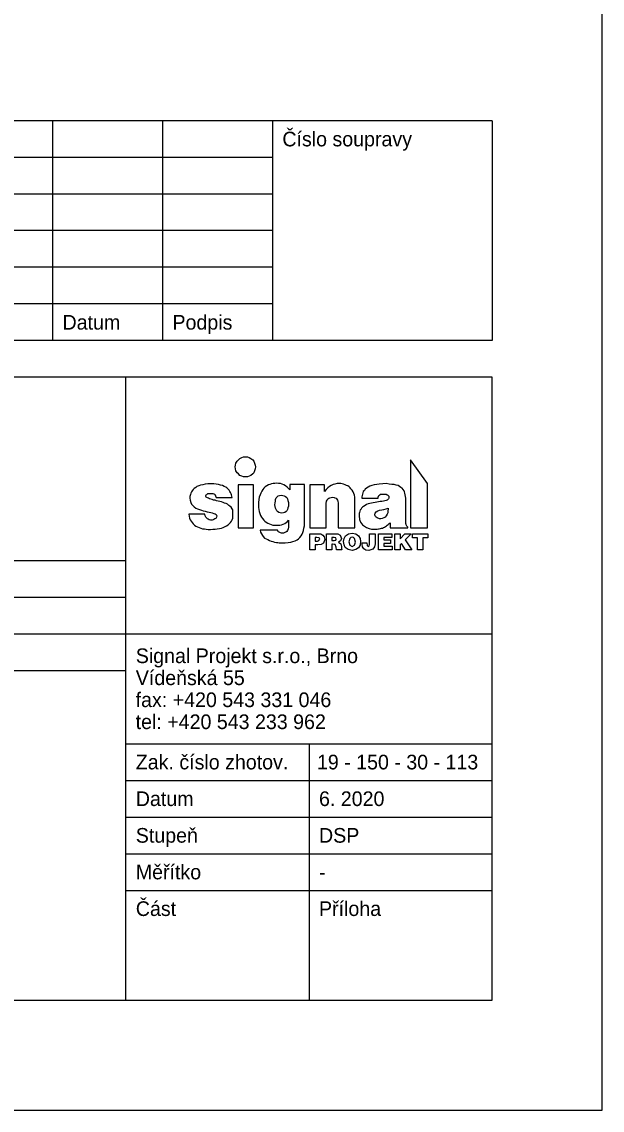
# Model space of a CAD drawing. Extents: x -790471 to -790261, y -983478 to -983181.
# Drawn here: x -790339.8 to -790260.6, y -983477.6 to -983329.1 of the extents above; entities that cross this region are included whole.
import ezdxf

# ---------------------------------------------------------------- set-up
doc = ezdxf.new("R2010")
doc.units = 0
for name, color, linetype in [('Info o rozpiskách', 7, 'Continuous'), ('popis', 7, 'Continuous'), ('Ramečky', 7, 'Continuous'), ('Rámečky-tisk', 7, 'Continuous'), ('Text', 7, 'Continuous')]:
    doc.layers.add(name, color=color, linetype=linetype)

msp = doc.modelspace()

# ---------------------------------------------------------------- linework, layer by layer
at = {"layer": 'Info o rozpiskách'}
for points in [[(-790309.25, -983388.46), (-790308.98, -983388.47), (-790308.76, -983388.57), (-790308.54, -983388.7), (-790308.29, -983388.87), (-790308.15, -983389.07), (-790308.03, -983389.31), (-790307.94, -983389.58), (-790307.92, -983389.84), (-790307.94, -983390.1), (-790308.03, -983390.38), (-790308.15, -983390.62), (-790308.29, -983390.79), (-790308.54, -983390.99), (-790308.76, -983391.09), (-790308.98, -983391.18), (-790309.25, -983391.2), (-790309.54, -983391.18), (-790309.79, -983391.09), (-790310.05, -983390.99), (-790310.23, -983390.79), (-790310.4, -983390.62), (-790310.57, -983390.38), (-790310.65, -983390.1), (-790310.7, -983389.84), (-790310.65, -983389.58), (-790310.57, -983389.31), (-790310.4, -983389.07), (-790310.23, -983388.87), (-790310.05, -983388.7), (-790309.79, -983388.57), (-790309.54, -983388.47), (-790309.25, -983388.46)], [(-790300.48, -983398.94), (-790299.41, -983398.94), (-790299, -983398.98), (-790298.7, -983399.13), (-790298.52, -983399.37), (-790298.46, -983399.72), (-790298.65, -983400.25), (-790298.95, -983400.42), (-790299.38, -983400.47), (-790299.75, -983400.47), (-790299.75, -983401.16), (-790300.48, -983401.16), (-790300.48, -983398.94)], [(-790299.75, -983399.44), (-790299.75, -983399.95), (-790299.43, -983399.95), (-790299.25, -983399.89), (-790299.15, -983399.69), (-790299.23, -983399.52), (-790299.54, -983399.44), (-790299.75, -983399.44)], [(-790298.24, -983398.94), (-790297.16, -983398.94), (-790296.67, -983398.98), (-790296.35, -983399.13), (-790296.19, -983399.58), (-790296.3, -983399.93), (-790296.56, -983400.12), (-790296.24, -983400.34), (-790296.19, -983400.71), (-790296.19, -983400.88), (-790296.17, -983401.05), (-790296.11, -983401.11), (-790296.11, -983401.16), (-790296.86, -983401.16), (-790296.9, -983400.77), (-790297.03, -983400.42), (-790297.18, -983400.4), (-790297.4, -983400.38), (-790297.51, -983400.38), (-790297.51, -983401.16), (-790298.24, -983401.16), (-790298.24, -983398.94)], [(-790297.51, -983399.44), (-790297.51, -983399.89), (-790297.19, -983399.89), (-790296.93, -983399.82), (-790296.88, -983399.69), (-790296.95, -983399.52), (-790297.16, -983399.44), (-790297.51, -983399.44)], [(-790294.73, -983398.89), (-790294.23, -983398.96), (-790293.84, -983399.22), (-790293.63, -983399.59), (-790293.56, -983400.02), (-790293.63, -983400.49), (-790293.85, -983400.86), (-790294.23, -983401.12), (-790294.73, -983401.22), (-790295.25, -983401.12), (-790295.65, -983400.84), (-790295.83, -983400.47), (-790295.91, -983400.02), (-790295.83, -983399.58), (-790295.61, -983399.22), (-790295.23, -983398.96), (-790294.73, -983398.89)], [(-790294.73, -983399.43), (-790294.92, -983399.46), (-790295.05, -983399.58), (-790295.16, -983400.04), (-790295.05, -983400.53), (-790294.73, -983400.68), (-790294.38, -983400.49), (-790294.28, -983400.08), (-790294.4, -983399.61), (-790294.53, -983399.46), (-790294.73, -983399.43)], [(-790292.33, -983398.94), (-790291.6, -983398.94), (-790291.6, -983400.32), (-790291.67, -983400.75), (-790291.88, -983401.05), (-790292.46, -983401.22), (-790292.83, -983401.18), (-790293.11, -983401.03), (-790293.29, -983400.75), (-790293.37, -983400.36), (-790293.35, -983400.19), (-790292.7, -983400.19), (-790292.66, -983400.56), (-790292.51, -983400.68), (-790292.38, -983400.6), (-790292.33, -983400.42), (-790292.33, -983398.94)], [(-790291.13, -983398.94), (-790289.32, -983398.94), (-790289.32, -983399.44), (-790290.4, -983399.44), (-790290.4, -983399.78), (-790289.49, -983399.78), (-790289.49, -983400.3), (-790290.4, -983400.3), (-790290.4, -983400.64), (-790289.27, -983400.64), (-790289.27, -983401.16), (-790291.13, -983401.16), (-790291.13, -983398.94)], [(-790288.91, -983398.94), (-790288.16, -983398.94), (-790288.16, -983399.65), (-790287.53, -983398.94), (-790286.67, -983398.94), (-790287.49, -983399.78), (-790286.58, -983401.16), (-790287.46, -983401.16), (-790288, -983400.28), (-790288.16, -983400.45), (-790288.16, -983401.16), (-790288.91, -983401.16), (-790288.91, -983398.94)], [(-790286.47, -983398.94), (-790284.41, -983398.94), (-790284.41, -983399.52), (-790285.07, -983399.52), (-790285.07, -983401.16), (-790285.8, -983401.16), (-790285.8, -983399.52), (-790286.47, -983399.52), (-790286.47, -983398.94)]]:
    msp.add_lwpolyline(points, dxfattribs=at)
at = {"layer": 'popis'}
for points in [[(-790286.77, -983388.87), (-790286.77, -983398.14), (-790284.45, -983398.14), (-790284.45, -983392.11), (-790286.77, -983388.87)], [(-790313.29, -983394.02), (-790311.09, -983394.02), (-790311.15, -983393.83), (-790311.19, -983393.66), (-790311.24, -983393.49), (-790311.32, -983393.33), (-790311.41, -983393.18), (-790311.52, -983393.01), (-790311.63, -983392.86), (-790311.8, -983392.69), (-790311.97, -983392.6), (-790312.17, -983392.49), (-790312.4, -983392.39), (-790312.66, -983392.3), (-790312.94, -983392.24), (-790313.26, -983392.19), (-790313.61, -983392.15), (-790314, -983392.13), (-790314.4, -983392.15), (-790314.77, -983392.19), (-790315.09, -983392.26), (-790315.4, -983392.32), (-790315.66, -983392.41), (-790315.89, -983392.52), (-790316.07, -983392.65), (-790316.26, -983392.78), (-790316.43, -983392.93), (-790316.54, -983393.08), (-790316.65, -983393.23), (-790316.71, -983393.4), (-790316.78, -983393.59), (-790316.82, -983393.75), (-790316.86, -983393.89), (-790316.86, -983394.09), (-790316.8, -983394.39), (-790316.71, -983394.69), (-790316.62, -983394.91), (-790316.43, -983395.15), (-790316.26, -983395.28), (-790316.06, -983395.45), (-790315.81, -983395.56), (-790315.55, -983395.64), (-790315.29, -983395.73), (-790315.03, -983395.81), (-790314.77, -983395.88), (-790314.51, -983395.96), (-790314.25, -983395.99), (-790314.02, -983396.03), (-790313.8, -983396.09), (-790313.59, -983396.18), (-790313.39, -983396.25), (-790313.29, -983396.33), (-790313.22, -983396.42), (-790313.2, -983396.52), (-790313.24, -983396.68), (-790313.29, -983396.76), (-790313.33, -983396.85), (-790313.44, -983396.93), (-790313.57, -983397), (-790313.67, -983397.04), (-790313.8, -983397.08), (-790313.93, -983397.08), (-790314.06, -983397.08), (-790314.21, -983397.04), (-790314.38, -983396.98), (-790314.47, -983396.93), (-790314.6, -983396.8), (-790314.69, -983396.68), (-790314.77, -983396.5), (-790314.82, -983396.27), (-790317.01, -983396.27), (-790316.97, -983396.57), (-790316.9, -983396.83), (-790316.8, -983397.06), (-790316.69, -983397.24), (-790316.56, -983397.43), (-790316.41, -983397.6), (-790316.24, -983397.77), (-790316.06, -983397.9), (-790315.83, -983398.01), (-790315.61, -983398.12), (-790315.38, -983398.2), (-790315.14, -983398.27), (-790314.86, -983398.29), (-790314.62, -983398.34), (-790314.38, -983398.36), (-790314.06, -983398.36), (-790313.74, -983398.34), (-790313.43, -983398.34), (-790313.13, -983398.29), (-790312.83, -983398.23), (-790312.55, -983398.18), (-790312.31, -983398.08), (-790312.06, -983397.95), (-790311.86, -983397.86), (-790311.65, -983397.73), (-790311.47, -983397.56), (-790311.34, -983397.41), (-790311.2, -983397.24), (-790311.09, -983397.06), (-790311.02, -983396.83), (-790311, -983396.61), (-790311, -983396.39), (-790311, -983396.33), (-790311, -983396.27), (-790311, -983396.22), (-790311, -983396.16), (-790311, -983396.09), (-790311, -983396.03), (-790311, -983395.99), (-790311, -983395.96), (-790311.02, -983395.71), (-790311.11, -983395.53), (-790311.24, -983395.34), (-790311.39, -983395.21), (-790311.54, -983395.08), (-790311.73, -983394.93), (-790311.9, -983394.84), (-790312.12, -983394.76), (-790312.32, -983394.69), (-790312.55, -983394.61), (-790312.77, -983394.54), (-790312.98, -983394.5), (-790313.22, -983394.44), (-790313.43, -983394.39), (-790313.65, -983394.35), (-790313.84, -983394.3), (-790314.02, -983394.22), (-790314.19, -983394.18), (-790314.32, -983394.11), (-790314.45, -983394.07), (-790314.53, -983394.02), (-790314.64, -983393.94), (-790314.67, -983393.89), (-790314.67, -983393.81), (-790314.67, -983393.74), (-790314.64, -983393.66), (-790314.56, -983393.59), (-790314.49, -983393.55), (-790314.41, -983393.47), (-790314.28, -983393.47), (-790314.13, -983393.44), (-790314, -983393.44), (-790313.85, -983393.44), (-790313.72, -983393.47), (-790313.61, -983393.49), (-790313.5, -983393.55), (-790313.43, -983393.64), (-790313.39, -983393.74), (-790313.31, -983393.85), (-790313.29, -983394.02)], [(-790303.24, -983392.24), (-790303.24, -983392.97), (-790303.41, -983392.77), (-790303.59, -983392.6), (-790303.8, -983392.43), (-790304.04, -983392.28), (-790304.28, -983392.17), (-790304.51, -983392.11), (-790304.75, -983392.08), (-790305.03, -983392.06), (-790305.29, -983392.08), (-790305.48, -983392.09), (-790305.74, -983392.13), (-790305.93, -983392.23), (-790306.15, -983392.28), (-790306.35, -983392.43), (-790306.58, -983392.54), (-790306.76, -983392.73), (-790306.91, -983392.92), (-790307.06, -983393.16), (-790307.19, -983393.4), (-790307.29, -983393.64), (-790307.4, -983393.96), (-790307.47, -983394.3), (-790307.51, -983394.67), (-790307.51, -983395.06), (-790307.51, -983395.38), (-790307.47, -983395.66), (-790307.4, -983395.92), (-790307.32, -983396.2), (-790307.23, -983396.44), (-790307.1, -983396.68), (-790306.93, -983396.89), (-790306.78, -983397.08), (-790306.62, -983397.24), (-790306.45, -983397.39), (-790306.22, -983397.52), (-790306, -983397.62), (-790305.78, -983397.71), (-790305.53, -983397.77), (-790305.29, -983397.8), (-790305.03, -983397.8), (-790304.81, -983397.8), (-790304.6, -983397.77), (-790304.34, -983397.73), (-790304.12, -983397.64), (-790303.91, -983397.54), (-790303.7, -983397.41), (-790303.56, -983397.28), (-790303.39, -983397.09), (-790303.39, -983397.64), (-790303.39, -983398.03), (-790303.46, -983398.29), (-790303.56, -983398.49), (-790303.63, -983398.64), (-790303.76, -983398.75), (-790303.91, -983398.79), (-790304.08, -983398.85), (-790304.26, -983398.85), (-790304.36, -983398.85), (-790304.49, -983398.83), (-790304.6, -983398.79), (-790304.69, -983398.75), (-790304.75, -983398.68), (-790304.84, -983398.61), (-790304.86, -983398.53), (-790304.9, -983398.44), (-790307.27, -983398.44), (-790307.21, -983398.74), (-790307.1, -983398.94), (-790306.97, -983399.17), (-790306.84, -983399.33), (-790306.67, -983399.54), (-790306.45, -983399.65), (-790306.24, -983399.74), (-790306, -983399.89), (-790305.78, -983399.97), (-790305.53, -983400.02), (-790305.31, -983400.08), (-790305.05, -983400.14), (-790304.84, -983400.15), (-790304.66, -983400.17), (-790304.43, -983400.19), (-790304.26, -983400.19), (-790303.85, -983400.17), (-790303.46, -983400.14), (-790303.09, -983400.08), (-790302.79, -983400.01), (-790302.49, -983399.91), (-790302.23, -983399.78), (-790302.03, -983399.63), (-790301.86, -983399.44), (-790301.69, -983399.24), (-790301.56, -983399.02), (-790301.45, -983398.77), (-790301.35, -983398.49), (-790301.32, -983398.2), (-790301.22, -983397.86), (-790301.22, -983397.51), (-790301.22, -983397.09), (-790301.22, -983392.24), (-790303.24, -983392.24)], [(-790300.5, -983392.26), (-790300.5, -983398.14), (-790298.26, -983398.14), (-790298.26, -983395.14), (-790298.26, -983394.82), (-790298.2, -983394.52), (-790298.11, -983394.35), (-790298.03, -983394.2), (-790297.9, -983394.11), (-790297.75, -983394.03), (-790297.57, -983394.02), (-790297.38, -983393.98), (-790297.19, -983394.02), (-790297.06, -983394.05), (-790296.9, -983394.11), (-790296.8, -983394.22), (-790296.73, -983394.35), (-790296.65, -983394.52), (-790296.62, -983394.78), (-790296.62, -983395.04), (-790296.62, -983398.14), (-790294.34, -983398.14), (-790294.34, -983394.59), (-790294.34, -983394.28), (-790294.36, -983393.98), (-790294.41, -983393.7), (-790294.51, -983393.44), (-790294.6, -983393.21), (-790294.71, -983393.01), (-790294.88, -983392.84), (-790294.99, -983392.67), (-790295.14, -983392.54), (-790295.31, -983392.41), (-790295.5, -983392.36), (-790295.68, -983392.26), (-790295.91, -983392.19), (-790296.09, -983392.15), (-790296.28, -983392.11), (-790296.5, -983392.11), (-790296.78, -983392.11), (-790297.06, -983392.19), (-790297.31, -983392.23), (-790297.57, -983392.36), (-790297.81, -983392.49), (-790298.05, -983392.67), (-790298.26, -983392.92), (-790298.5, -983393.18), (-790298.5, -983392.26), (-790300.5, -983392.26)], [(-790293.41, -983394.11), (-790291.19, -983394.11), (-790291.17, -983393.94), (-790291.13, -983393.81), (-790291.06, -983393.72), (-790290.96, -983393.64), (-790290.85, -983393.57), (-790290.7, -983393.53), (-790290.57, -983393.53), (-790290.42, -983393.53), (-790290.25, -983393.53), (-790290.09, -983393.55), (-790289.96, -983393.62), (-790289.88, -983393.66), (-790289.81, -983393.74), (-790289.73, -983393.81), (-790289.73, -983393.9), (-790289.69, -983394), (-790289.73, -983394.09), (-790289.75, -983394.2), (-790289.84, -983394.28), (-790289.94, -983394.35), (-790290.07, -983394.43), (-790290.25, -983394.46), (-790290.46, -983394.5), (-790290.66, -983394.54), (-790290.89, -983394.56), (-790291.13, -983394.59), (-790291.36, -983394.63), (-790291.6, -983394.67), (-790291.84, -983394.73), (-790292.08, -983394.76), (-790292.29, -983394.84), (-790292.51, -983394.87), (-790292.74, -983394.97), (-790292.96, -983395.08), (-790293.15, -983395.23), (-790293.31, -983395.32), (-790293.44, -983395.47), (-790293.54, -983395.62), (-790293.61, -983395.71), (-790293.67, -983395.88), (-790293.7, -983396.03), (-790293.74, -983396.2), (-790293.76, -983396.35), (-790293.76, -983396.52), (-790293.7, -983397), (-790293.56, -983397.39), (-790293.31, -983397.73), (-790293.05, -983397.93), (-790292.74, -983398.12), (-790292.38, -983398.25), (-790292.06, -983398.33), (-790291.73, -983398.34), (-790291.58, -983398.34), (-790291.45, -983398.33), (-790291.3, -983398.33), (-790291.13, -983398.29), (-790291.02, -983398.27), (-790290.85, -983398.25), (-790290.7, -983398.21), (-790290.57, -983398.18), (-790290.44, -983398.1), (-790290.31, -983398.03), (-790290.18, -983397.97), (-790290.03, -983397.88), (-790289.92, -983397.78), (-790289.81, -983397.67), (-790289.66, -983397.56), (-790289.55, -983397.47), (-790289.51, -983398.16), (-790287.12, -983398.16), (-790287.12, -983398.06), (-790287.25, -983397.93), (-790287.31, -983397.84), (-790287.36, -983397.75), (-790287.36, -983397.67), (-790287.4, -983397.56), (-790287.4, -983397.49), (-790287.4, -983397.37), (-790287.4, -983397.23), (-790287.4, -983394.35), (-790287.4, -983394.11), (-790287.46, -983393.87), (-790287.49, -983393.64), (-790287.53, -983393.42), (-790287.59, -983393.23), (-790287.64, -983393.08), (-790287.74, -983392.92), (-790287.9, -983392.75), (-790288.07, -983392.62), (-790288.24, -983392.51), (-790288.46, -983392.39), (-790288.71, -983392.3), (-790288.97, -983392.24), (-790289.3, -983392.21), (-790289.66, -983392.17), (-790290.07, -983392.11), (-790290.53, -983392.13), (-790291.02, -983392.17), (-790291.37, -983392.23), (-790291.73, -983392.28), (-790292.05, -983392.37), (-790292.29, -983392.47), (-790292.53, -983392.6), (-790292.74, -983392.73), (-790292.92, -983392.88), (-790293.05, -983393.03), (-790293.2, -983393.2), (-790293.28, -983393.38), (-790293.31, -983393.53), (-790293.37, -983393.72), (-790293.41, -983393.9), (-790293.41, -983394.11)], [(-790310.27, -983392.26), (-790310.27, -983398.14), (-790308.18, -983398.14), (-790308.18, -983392.26), (-790310.27, -983392.26)], [(-790304.39, -983393.7), (-790304.19, -983393.74), (-790303.98, -983393.79), (-790303.8, -983393.89), (-790303.65, -983394.02), (-790303.56, -983394.2), (-790303.48, -983394.41), (-790303.41, -983394.67), (-790303.41, -983394.95), (-790303.41, -983395.19), (-790303.48, -983395.42), (-790303.54, -983395.64), (-790303.63, -983395.81), (-790303.74, -983395.92), (-790303.91, -983396.05), (-790304.08, -983396.11), (-790304.3, -983396.12), (-790304.53, -983396.11), (-790304.71, -983396.05), (-790304.9, -983395.92), (-790305.01, -983395.83), (-790305.1, -983395.64), (-790305.2, -983395.47), (-790305.23, -983395.25), (-790305.25, -983395.01), (-790305.23, -983394.74), (-790305.2, -983394.5), (-790305.16, -983394.28), (-790305.09, -983394.07), (-790304.99, -983393.94), (-790304.82, -983393.79), (-790304.64, -983393.74), (-790304.39, -983393.7)], [(-790289.81, -983395.47), (-790289.81, -983395.49), (-790289.81, -983395.55), (-790289.81, -983395.58), (-790289.84, -983395.84), (-790289.86, -983396.11), (-790289.96, -983396.29), (-790290.07, -983396.52), (-790290.22, -983396.68), (-790290.4, -983396.78), (-790290.61, -983396.87), (-790290.81, -983396.93), (-790290.98, -983396.93), (-790291.09, -983396.89), (-790291.21, -983396.83), (-790291.32, -983396.78), (-790291.43, -983396.7), (-790291.52, -983396.61), (-790291.6, -983396.52), (-790291.62, -983396.37), (-790291.58, -983396.12), (-790291.45, -983395.94), (-790291.22, -983395.83), (-790290.98, -983395.75), (-790290.66, -983395.68), (-790290.38, -983395.64), (-790290.09, -983395.55), (-790289.81, -983395.47)]]:
    msp.add_lwpolyline(points, dxfattribs=at)
at = {"layer": 'Ramečky'}
for p, q in [((-790275.59, -983342.6), (-790455.59, -983342.6)), ((-790335.59, -983342.6), (-790335.59, -983372.6)), ((-790320.59, -983342.6), (-790320.59, -983372.6)), ((-790305.59, -983342.6), (-790305.59, -983372.6)), ((-790275.59, -983342.6), (-790275.59, -983372.6)), ((-790305.59, -983347.6), (-790455.59, -983347.6)), ((-790305.59, -983352.6), (-790455.59, -983352.6)), ((-790305.59, -983357.6), (-790455.59, -983357.6)), ((-790305.59, -983362.6), (-790455.59, -983362.6)), ((-790305.59, -983367.6), (-790455.59, -983367.6)), ((-790275.59, -983372.6), (-790455.59, -983372.6)), ((-790275.59, -983377.6), (-790455.59, -983377.6)), ((-790325.59, -983462.6), (-790325.59, -983377.6)), ((-790275.59, -983462.6), (-790275.59, -983377.6)), ((-790455.59, -983402.6), (-790325.59, -983402.6)), ((-790455.59, -983407.6), (-790325.59, -983407.6)), ((-790455.59, -983412.6), (-790325.59, -983412.6)), ((-790455.59, -983417.6), (-790325.59, -983417.6)), ((-790325.59, -983427.6), (-790275.59, -983427.6)), ((-790325.59, -983432.6), (-790275.59, -983432.6)), ((-790325.59, -983437.6), (-790275.59, -983437.6)), ((-790325.59, -983442.6), (-790275.59, -983442.6)), ((-790325.6, -983447.6), (-790275.59, -983447.6)), ((-790455.59, -983462.6), (-790275.59, -983462.6))]:
    msp.add_line(p, q, dxfattribs=at)
for points in [[(-790325.59, -983412.6), (-790275.59, -983412.6)], [(-790300.59, -983427.6), (-790300.59, -983462.6)]]:
    msp.add_lwpolyline(points, dxfattribs=at)
at = {"layer": 'Rámečky-tisk'}
msp.add_lwpolyline([(-790470.59, -983477.6), (-790260.59, -983477.6), (-790260.59, -983180.6)], dxfattribs=at)

# ---------------------------------------------------------------- texts
at = {"layer": 'Text'}
for s, p in [('Číslo soupravy', (-790304.24, -983346.1)), ('Datum', (-790334.24, -983371.1)), ('Podpis', (-790319.24, -983371.1)), ('Signal Projekt s.r.o., Brno', (-790324.24, -983416.6)), ('Vídeňská 55', (-790324.24, -983419.6)), ('fax: +420 543 331 046', (-790324.26, -983422.6)), ('tel: +420 543 233 962', (-790324.26, -983425.6)), ('Zak. číslo zhotov.', (-790324.24, -983431.1)), ('19 - 150 - 30 - 113', (-790299.52, -983431.1)), ('Datum', (-790324.24, -983436.1)), ('6. 2020', (-790299.24, -983436.1)), ('Stupeň', (-790324.24, -983441.1)), ('DSP', (-790299.24, -983441.1)), ('Měřítko', (-790324.24, -983446.1)), ('-', (-790299.24, -983446.1)), ('Část', (-790324.24, -983451.1)), ('Příloha', (-790299.24, -983451.1))]:
    msp.add_text(s, height=2, dxfattribs=at).set_placement(p)

doc.saveas('drawing.dxf')
